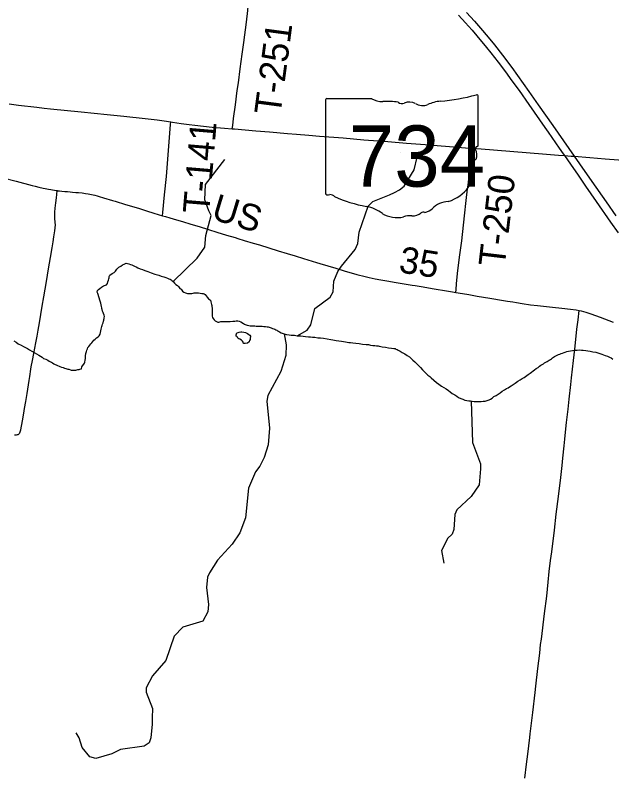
# Model space of a CAD drawing. Extents: x -5.4 to 49.9, y 13.2 to 48.4.
# Drawn here: x 30.593 to 31.879, y 42.099 to 43.736 of the extents above; entities that cross this region are included whole.
import ezdxf

# ---------------------------------------------------------------- set-up
doc = ezdxf.new("R2010")
doc.units = 0
for name, color, linetype in [('GM_X_County_Road', 7, 'Continuous'), ('GM_X_County_Road_Text', 7, 'Continuous'), ('GM_X_Minor_Lake', 7, 'Continuous'), ('GM_X_Minor_River', 7, 'Continuous'), ('GM_X_State_Location', 7, 'Continuous'), ('GM_X_State_Route', 7, 'Continuous'), ('GM_X_State_Shield', 7, 'Continuous'), ('GM_X_Township_Road', 7, 'Continuous'), ('GM_X_Township_Road_Text', 7, 'Continuous'), ('GM_X_US_Route', 7, 'Continuous')]:
    doc.layers.add(name, color=color, linetype=linetype)

msp = doc.modelspace()

# ---------------------------------------------------------------- linework, layer by layer
at = {"layer": 'GM_X_County_Road'}
for points in [[(30.5673, 43.3856), (30.595, 43.3783), (30.6298, 43.3691), (30.6358, 43.3675), (30.6442, 43.3654), (30.6533, 43.3633), (30.6575, 43.3623), (30.6648, 43.3608), (30.6697, 43.36), (30.673, 43.3593), (30.6774, 43.3586), (30.6811, 43.3581), (30.6833, 43.3579)], [(30.6833, 43.3579), (30.6843, 43.3577), (30.6888, 43.3574), (30.6938, 43.3569), (30.6999, 43.3563), (30.7055, 43.3558), (30.7117, 43.3553), (30.7166, 43.3548), (30.7234, 43.3542), (30.7296, 43.3536), (30.7376, 43.3528), (30.7444, 43.3519), (30.7505, 43.351), (30.7571, 43.3496), (30.7644, 43.348), (30.7698, 43.3466), (30.7739, 43.3454), (30.7835, 43.3426), (30.8025, 43.3369), (30.8084, 43.3351), (30.831, 43.3282), (30.8434, 43.3244), (30.8607, 43.3191), (30.8761, 43.3144), (30.8915, 43.3096), (30.9106, 43.3038), (30.9108, 43.3038)], [(30.9108, 43.3038), (30.9171, 43.3019), (30.9261, 43.2993), (30.9409, 43.2949), (30.9534, 43.2912), (30.9713, 43.2858), (30.9897, 43.2803), (31.0099, 43.2741), (31.0277, 43.2686), (31.0486, 43.2623), (31.067, 43.2568), (31.0729, 43.255), (31.0866, 43.2508), (31.1062, 43.245), (31.1198, 43.2409), (31.1394, 43.2349), (31.1601, 43.2284), (31.1791, 43.2226), (31.1963, 43.2174), (31.2148, 43.2118), (31.2428, 43.2034), (31.2499, 43.2012), (31.2671, 43.196), (31.2844, 43.1908), (31.3022, 43.1854), (31.3297, 43.1774), (31.3471, 43.1727), (31.3562, 43.1706), (31.369, 43.168), (31.3812, 43.1659), (31.3941, 43.1636), (31.4139, 43.1602), (31.4487, 43.1544), (31.4555, 43.1533), (31.4684, 43.1512), (31.4959, 43.1466), (31.5229, 43.1421), (31.5357, 43.1399), (31.5426, 43.1387)], [(31.5426, 43.1387), (31.5572, 43.1362), (31.5706, 43.134), (31.589, 43.1309), (31.6159, 43.1263), (31.6459, 43.1212), (31.6539, 43.1199), (31.6656, 43.118), (31.6735, 43.1167), (31.6858, 43.1147), (31.7036, 43.1121), (31.7191, 43.1102), (31.7512, 43.1068), (31.7716, 43.1047), (31.7901, 43.1028), (31.8024, 43.101), (31.8087, 43.0998)], [(31.6918, 42.0924), (31.6955, 42.1226), (31.6982, 42.1442), (31.7024, 42.18), (31.7034, 42.188), (31.7089, 42.2337), (31.7138, 42.2769), (31.7155, 42.2905), (31.7199, 42.3287), (31.7236, 42.3615), (31.7257, 42.38), (31.7272, 42.3917), (31.7341, 42.4472), (31.7388, 42.4843), (31.7418, 42.5144), (31.7443, 42.5373), (31.7471, 42.5608), (31.7495, 42.5799), (31.7552, 42.6262), (31.7593, 42.6607), (31.7642, 42.6989), (31.7691, 42.7402), (31.772, 42.7656), (31.7737, 42.7816), (31.7765, 42.8082), (31.778, 42.8224), (31.7795, 42.8378), (31.7816, 42.8582), (31.7849, 42.8873), (31.7874, 42.9089), (31.7906, 42.9404), (31.7922, 42.9546), (31.7966, 42.9922), (31.8001, 43.0231), (31.804, 43.0596), (31.8064, 43.0799), (31.8087, 43.0998)], [(31.8087, 43.0998), (31.8133, 43.0989), (31.8234, 43.0962), (31.834, 43.0927), (31.8537, 43.0852), (31.8822, 43.0743)]]:
    msp.add_lwpolyline(points, dxfattribs=at)
at = {"layer": 'GM_X_Minor_Lake'}
msp.add_lwpolyline([(31.0712, 43.0518), (31.0757, 43.0532), (31.0792, 43.0536), (31.0814, 43.0539), (31.086, 43.0527), (31.0894, 43.0523), (31.092, 43.0511), (31.0939, 43.0504), (31.0969, 43.048), (31.0988, 43.0465), (31.1003, 43.0442), (31.0995, 43.0397), (31.0995, 43.037), (31.0983, 43.0347), (31.0971, 43.0321), (31.0937, 43.0295), (31.0884, 43.0288), (31.0853, 43.0284), (31.0842, 43.0315), (31.0831, 43.0334), (31.0805, 43.0361), (31.0775, 43.0376), (31.0748, 43.0388), (31.0726, 43.04), (31.0711, 43.0426), (31.0696, 43.0446), (31.0696, 43.0472), (31.0708, 43.0518), (31.0712, 43.0518)], dxfattribs=at)
at = {"layer": 'GM_X_Minor_River'}
for points in [[(31.2009, 43.0454), (31.2224, 43.0576), (31.2306, 43.0689), (31.2392, 43.1037), (31.2722, 43.1281), (31.2781, 43.1398), (31.28, 43.1629), (31.2887, 43.184), (31.2965, 43.1949), (31.3259, 43.2312), (31.3315, 43.244), (31.3346, 43.2683), (31.3541, 43.3241), (31.3638, 43.3342), (31.4, 43.3487), (31.4104, 43.3542), (31.4215, 43.3594), (31.4311, 43.3672), (31.4529, 43.4025), (31.4598, 43.4297)], [(30.9335, 43.162), (30.9853, 43.2127), (31.0016, 43.236), (31.0036, 43.261), (31.0157, 43.3045), (31.0102, 43.3141), (31.0019, 43.3378), (31.0029, 43.3708), (31.0448, 43.4247)], [(30.6993, 42.9758), (30.7019, 42.975), (30.7042, 42.9742), (30.7065, 42.9734), (30.7084, 42.973), (30.7118, 42.9718), (30.7136, 42.9714), (30.7159, 42.971), (30.7182, 42.971), (30.7205, 42.971), (30.7239, 42.9713), (30.7277, 42.9724), (30.7307, 42.9728), (30.7326, 42.9731), (30.7357, 42.9738), (30.7369, 42.9784), (30.7423, 42.9859), (30.7427, 42.9886), (30.7435, 42.9927), (30.7443, 42.9965), (30.7447, 43.0019), (30.7455, 43.0068), (30.7459, 43.0094), (30.7463, 43.0117), (30.7471, 43.014), (30.7487, 43.017), (30.7498, 43.0197), (30.7517, 43.0219), (30.7541, 43.0249), (30.756, 43.0276), (30.7579, 43.0298), (30.7602, 43.0328), (30.7625, 43.0358), (30.7656, 43.0381), (30.7683, 43.0407), (30.7717, 43.043), (30.774, 43.0448), (30.7763, 43.0486), (30.7771, 43.0524), (30.7775, 43.0558), (30.7783, 43.0592), (30.7791, 43.0623), (30.7799, 43.0653), (30.7807, 43.0676), (30.7815, 43.0702), (30.7823, 43.0729), (30.7831, 43.0767), (30.7838, 43.0785), (30.7842, 43.0804), (30.7846, 43.0823), (30.785, 43.0842), (30.7851, 43.0869), (30.7847, 43.0896), (30.7836, 43.093), (30.7825, 43.0957), (30.7814, 43.0983), (30.7807, 43.1018), (30.7799, 43.1037), (30.78, 43.1056), (30.7792, 43.1082), (30.7785, 43.1117), (30.7778, 43.1158), (30.7763, 43.1197), (30.7708, 43.1364), (30.7697, 43.1391), (30.7705, 43.1425), (30.7728, 43.1452), (30.7751, 43.147), (30.7789, 43.15), (30.7808, 43.1515), (30.7831, 43.1526), (30.7858, 43.1538), (30.7877, 43.1545), (30.7896, 43.1552), (30.7919, 43.1582), (30.7927, 43.1617), (30.7939, 43.1651), (30.7947, 43.1677), (30.7954, 43.1704), (30.7958, 43.1726), (30.797, 43.1757), (30.802, 43.1794), (30.8066, 43.1813), (30.8089, 43.1846), (30.8123, 43.1884), (30.8162, 43.1929), (30.8208, 43.1955), (30.8242, 43.1982), (30.828, 43.1996), (30.8322, 43.2019), (30.8379, 43.1999), (30.8417, 43.1987), (30.8447, 43.1979), (30.8469, 43.1964), (30.85, 43.1952), (30.8537, 43.1936), (30.8575, 43.1917), (30.8624, 43.1897), (30.8673, 43.1878), (30.8726, 43.1855), (30.8791, 43.1835)], [(30.8791, 43.1835), (30.8859, 43.1807), (30.8938, 43.178), (30.9029, 43.1756), (30.9078, 43.1737), (30.9131, 43.1721), (30.9176, 43.1705), (30.9214, 43.1693), (30.9244, 43.1682), (30.9271, 43.167), (30.9289, 43.1654), (30.9312, 43.1639), (30.9335, 43.162), (30.9361, 43.1589), (30.9391, 43.1554), (30.9429, 43.1535), (30.9447, 43.1516), (30.9462, 43.1493), (30.9481, 43.1474), (30.9504, 43.1454), (30.9519, 43.1435), (30.9534, 43.1416), (30.9564, 43.1389), (30.9598, 43.1374), (30.9643, 43.1365), (30.9681, 43.1365), (30.9715, 43.1365), (30.9738, 43.1364), (30.9765, 43.1372), (30.9787, 43.1375), (30.9882, 43.1374), (30.9916, 43.137), (30.995, 43.1366), (30.9985, 43.1362), (31.0003, 43.1358), (31.0026, 43.1338), (31.0045, 43.1315), (31.0071, 43.1281), (31.0097, 43.125), (31.012, 43.1231), (31.0139, 43.1219), (31.0146, 43.1181), (31.0157, 43.1158), (31.0164, 43.1124), (31.0168, 43.1105), (31.0171, 43.1086), (31.0175, 43.1048), (31.0174, 43.1014), (31.0174, 43.098), (31.0174, 43.0938), (31.0177, 43.0904), (31.0177, 43.0877), (31.0184, 43.0846), (31.0195, 43.0824), (31.0218, 43.0797), (31.024, 43.0777), (31.0267, 43.0762), (31.0297, 43.0746), (31.0316, 43.0746), (31.0361, 43.0757), (31.0422, 43.076), (31.0502, 43.0759), (31.0563, 43.0762), (31.0619, 43.0766), (31.0661, 43.0769), (31.0695, 43.0772), (31.0726, 43.0772), (31.076, 43.0768), (31.079, 43.0756), (31.085, 43.0717), (31.0869, 43.0702), (31.0888, 43.0694), (31.0907, 43.0686), (31.0933, 43.0678), (31.0964, 43.0674), (31.0994, 43.067), (31.1021, 43.067), (31.1062, 43.0666), (31.1093, 43.0665), (31.1123, 43.0661), (31.1153, 43.0661), (31.1188, 43.066), (31.1218, 43.066), (31.1252, 43.0656), (31.129, 43.0655), (31.1328, 43.0651), (31.1358, 43.0647), (31.1385, 43.0643), (31.1404, 43.0639), (31.1426, 43.0631), (31.1449, 43.0623), (31.1475, 43.0612), (31.1506, 43.06), (31.1528, 43.0592), (31.1547, 43.058), (31.1566, 43.0573), (31.1585, 43.0561), (31.1604, 43.0549), (31.163, 43.0534), (31.1664, 43.0518), (31.1725, 43.0495)], [(31.1725, 43.0495), (31.1768, 43.0254), (31.1764, 43.003), (31.1659, 42.9686), (31.1373, 42.9164), (31.1352, 42.9043), (31.1414, 42.8464), (31.1381, 42.81), (31.13, 42.7832), (31.1206, 42.764), (31.1109, 42.7524), (31.0959, 42.717), (31.0894, 42.6533), (31.0771, 42.6205), (31.0604, 42.5961), (31.0294, 42.5617), (31.0119, 42.5347), (31.0075, 42.5249), (31.0053, 42.5029), (31.0095, 42.466), (31.0081, 42.4509), (30.9972, 42.4305), (30.9541, 42.4177), (30.9359, 42.3979), (30.9176, 42.3458), (30.8886, 42.3129), (30.8752, 42.2869), (30.8751, 42.2774), (30.8888, 42.2426), (30.8881, 42.2221), (30.8882, 42.2088), (30.8854, 42.1789), (30.8815, 42.1687), (30.8707, 42.1609), (30.8202, 42.1539), (30.8011, 42.1444), (30.7668, 42.1347), (30.7536, 42.138), (30.7376, 42.1584), (30.7308, 42.1794), (30.7242, 42.1898)], [(31.1725, 43.0495), (31.1781, 43.0479), (31.1838, 43.0471), (31.188, 43.0466), (31.1914, 43.0462), (31.1948, 43.0462), (31.1978, 43.0458), (31.2009, 43.0454), (31.2047, 43.0453), (31.2088, 43.0449), (31.2138, 43.0445), (31.2187, 43.0436), (31.2251, 43.0432), (31.2297, 43.0428), (31.2342, 43.0423), (31.2392, 43.0419), (31.2452, 43.0411), (31.2513, 43.0406), (31.2573, 43.0398), (31.2733, 43.0373), (31.2778, 43.0365), (31.2846, 43.0353), (31.2964, 43.0333), (31.3051, 43.032), (31.3123, 43.0308), (31.3161, 43.0304), (31.321, 43.0303), (31.3274, 43.0295), (31.3342, 43.0283), (31.3414, 43.0271), (31.3498, 43.0266), (31.3543, 43.0262), (31.3589, 43.025), (31.3638, 43.0245), (31.3684, 43.0241), (31.3718, 43.0233), (31.3752, 43.0233), (31.3775, 43.0232), (31.3812, 43.0221), (31.3843, 43.0216), (31.3911, 43.0208), (31.3975, 43.0196), (31.404, 43.0184), (31.4089, 43.0179), (31.4119, 43.0175), (31.4138, 43.0167), (31.4161, 43.016), (31.4187, 43.0144), (31.4225, 43.0121), (31.4274, 43.0094), (31.4327, 43.0063), (31.4376, 43.0024), (31.4428, 42.9997), (31.4466, 42.9966), (31.4504, 42.9928), (31.4545, 42.9893), (31.4579, 42.9855), (31.462, 42.9812), (31.4665, 42.977), (31.471, 42.972), (31.4751, 42.9674), (31.4793, 42.9636), (31.4827, 42.9605), (31.4868, 42.9574), (31.4898, 42.9543), (31.5011, 42.9447), (31.5064, 42.9412), (31.5116, 42.937), (31.5173, 42.9335), (31.5222, 42.9308), (31.5267, 42.9277), (31.5308, 42.9246), (31.5346, 42.9208), (31.5406, 42.918), (31.5448, 42.915), (31.5489, 42.9126), (31.5535, 42.9103), (31.558, 42.9084), (31.5625, 42.9068), (31.5667, 42.906), (31.5705, 42.9052), (31.5735, 42.9048), (31.5758, 42.9047), (31.5781, 42.9043), (31.5822, 42.9039), (31.5853, 42.9039), (31.5883, 42.9038), (31.5928, 42.9038), (31.5978, 42.9037), (31.602, 42.9041), (31.6061, 42.9044), (31.6103, 42.9055), (31.6145, 42.907), (31.6176, 42.9088), (31.621, 42.9111), (31.6248, 42.9144), (31.6298, 42.9167), (31.634, 42.9197), (31.6382, 42.9226), (31.6424, 42.9256), (31.6478, 42.929)], [(30.5902, 43.034), (30.5948, 43.0313), (30.5993, 43.0282), (30.6061, 43.0247), (30.6106, 43.022), (30.6151, 43.02), (30.6193, 43.0177), (30.6238, 43.015), (30.6291, 43.0119), (30.6442, 43.0034), (30.6476, 43.0014), (30.651, 42.9991), (30.6543, 42.9964), (30.6593, 42.9945), (30.663, 42.9925), (30.666, 42.9906), (30.6687, 42.9894), (30.671, 42.9882), (30.6736, 42.9867), (30.6762, 42.9851), (30.6789, 42.9836), (30.6815, 42.9824), (30.6838, 42.9813), (30.6876, 42.9797), (30.6894, 42.9789), (30.6925, 42.9777), (30.6962, 42.9766), (30.6993, 42.9758)], [(31.6478, 42.929), (31.6523, 42.9316), (31.6558, 42.9331), (31.6584, 42.935), (31.6619, 42.9376), (31.6661, 42.9406), (31.6707, 42.9432), (31.6768, 42.9473), (31.6818, 42.9503), (31.686, 42.9529), (31.6898, 42.9551), (31.6928, 42.9578), (31.6959, 42.9596), (31.699, 42.9619), (31.7028, 42.9645), (31.7127, 42.9716), (31.7162, 42.9746), (31.72, 42.9772), (31.723, 42.9798), (31.7261, 42.9817), (31.7288, 42.9836), (31.7315, 42.9851), (31.7341, 42.9869), (31.7372, 42.9884), (31.7395, 42.9899), (31.7421, 42.9914), (31.7441, 42.9925), (31.7471, 42.994), (31.749, 42.9959), (31.7509, 42.9974), (31.7532, 42.9989), (31.7555, 43.0004), (31.7582, 43.0019), (31.7612, 43.0037), (31.7643, 43.0048), (31.7673, 43.0059), (31.77, 43.007), (31.7727, 43.0081), (31.7761, 43.0092), (31.7788, 43.01), (31.7822, 43.0111), (31.7856, 43.0118), (31.7898, 43.0129), (31.7944, 43.0136), (31.7993, 43.0139), (31.8046, 43.0142), (31.8095, 43.0146), (31.8137, 43.0145), (31.8175, 43.0141), (31.8232, 43.0133), (31.8274, 43.0125), (31.8323, 43.012), (31.8384, 43.0108), (31.8448, 43.0096), (31.8512, 43.008), (31.8576, 43.0053), (31.8644, 43.0029), (31.8701, 43.001), (31.8743, 42.999), (31.8777, 42.9975), (31.8811, 42.9948)], [(31.5758, 42.9047), (31.5789, 42.8153), (31.5959, 42.7694), (31.5961, 42.7588), (31.5932, 42.7239), (31.5757, 42.6991), (31.5449, 42.6701), (31.5405, 42.6599), (31.5384, 42.628), (31.5348, 42.6175), (31.5252, 42.6085), (31.5193, 42.5961), (31.5122, 42.5826), (31.517, 42.5555)]]:
    msp.add_lwpolyline(points, dxfattribs=at)
at = {"layer": 'GM_X_State_Route'}
for points in [[(30.5797, 43.5446), (30.6001, 43.5422), (30.6395, 43.5374), (30.6556, 43.5357), (30.6692, 43.5342), (30.7353, 43.5274), (30.7915, 43.5216), (30.8268, 43.518), (30.8733, 43.5132), (30.8993, 43.5102), (30.9141, 43.5083), (30.9283, 43.5063), (30.932, 43.5057), (30.951, 43.5026), (30.9682, 43.5), (30.9799, 43.4986), (31.0176, 43.4949), (31.0442, 43.4928), (31.0609, 43.4913), (31.0659, 43.4909), (31.1117, 43.4867), (31.1408, 43.4843), (31.1798, 43.4809), (31.1996, 43.4792), (31.2262, 43.4773), (31.2492, 43.4755), (31.2999, 43.4714), (31.3445, 43.4676), (31.3965, 43.4636), (31.4362, 43.4605), (31.4765, 43.4573), (31.5551, 43.4509), (31.572, 43.4497)], [(31.572, 43.4497), (31.578, 43.4492), (31.5978, 43.4477), (31.6944, 43.4399), (31.7384, 43.4366), (31.7644, 43.4345)], [(31.7644, 43.4345), (31.777, 43.4335), (31.7917, 43.4324), (31.7981, 43.4318), (31.832, 43.4291), (31.8648, 43.4267), (31.9515, 43.4199), (32.0544, 43.4114)]]:
    msp.add_lwpolyline(points, dxfattribs=at)
at = {"layer": 'GM_X_State_Shield'}
for p, q in [((31.5913, 43.4563), (31.5913, 43.5609)), ((31.2617, 43.5525), (31.2617, 43.3524)), ((31.3615, 43.556), (31.2649, 43.556)), ((31.5912, 43.4563), (31.5913, 43.4563))]:
    msp.add_line(p, q, dxfattribs=at)
for centre, major_axis, start_param, end_param in [((31.4739, 43.8288), (0.3495, 0), 4.814394, 5.042369), ((31.5876, 43.5614), (0.00367, 0), 6.141152, 7.989035), ((31.2655, 43.553), (0.00382, 0), 1.712693, 3.28349), ((31.3844, 43.5792), (0.037, 0), 4.042523, 4.731795), ((31.3967, 43.4436), (0.133, 0), 1.404758, 1.657858), ((31.4269, 43.554), (0.0107, 0), 3.836095, 5.185415), ((31.4426, 43.5309), (0.0222, 0), 0.950623, 2.079405), ((31.4713, 43.5626), (0.0267, 0), 4.081561, 5.145723), ((31.5184, 43.4949), (0.0703, 0), 1.699011, 2.107814), ((31.5904, 43.4486), (0.00568, 0), 1.883978, 3.671073), ((31.5543, 43.4353), (0.0341, 0), 5.934695, 6.695948), ((31.5874, 43.4559), (0.00393, 0), 5.05454, 6.418171), ((31.6044, 43.4125), (0.0248, 0), 2.387724, 3.262537), ((31.4934, 43.3991), (0.0874, 0), 5.101752, 6.440018), ((31.2655, 43.352), (0.00385, 0), 3.00124, 4.508301), ((31.2661, 43.3725), (0.0294, 0), 4.665946, 4.897461), ((31.2721, 43.3409), (0.0106, 0), 0.519207, 1.627899), ((31.4059, 43.5207), (0.2524, 0), 4.195997, 4.488961), ((31.5303, 43.2962), (0.0479, 0), 1.647645, 2.488434), ((31.3307, 43.2625), (0.079, 0), 0.823519, 1.323587), ((31.4696, 43.333), (0.0282, 0), 4.937069, 5.64225), ((31.4161, 43.3399), (0.0501, 0), 4.026481, 4.996735), ((31.445, 43.2707), (0.0412, 0), 1.495662, 1.94098), ((31.4487, 43.3249), (0.0267, 0), 4.691044, 5.507374), ((31.4728, 43.3055), (0.00752, 0), 1.147584, 2.315152)]:
    msp.add_ellipse(centre, major_axis=major_axis, ratio=0.8, start_param=start_param, end_param=end_param, dxfattribs=at)
at = {"layer": 'GM_X_Township_Road'}
for points in [[(31.0609, 43.4913), (31.0618, 43.4981), (31.0639, 43.5135), (31.0675, 43.5425), (31.0717, 43.5733), (31.074, 43.5899), (31.0781, 43.6201), (31.0824, 43.6521), (31.0859, 43.6767), (31.0916, 43.7211), (31.0945, 43.7458), (31.0962, 43.765), (31.0975, 43.7811), (31.1004, 43.8176), (31.1045, 43.8672), (31.1061, 43.8887)], [(30.9108, 43.3038), (30.9115, 43.3111), (30.9148, 43.3492), (30.9189, 43.3885), (30.9257, 43.4725), (30.9278, 43.5003), (30.9283, 43.5063)], [(31.5682, 43.3619), (31.5692, 43.37), (31.5734, 43.4095), (31.577, 43.4403), (31.578, 43.4492)], [(30.6394, 43.0406), (30.6401, 43.0445), (30.6424, 43.0574), (30.6453, 43.0732), (30.6512, 43.1087), (30.6545, 43.129), (30.6601, 43.162), (30.6646, 43.1895), (30.6688, 43.214), (30.6725, 43.2348), (30.6747, 43.2477), (30.6764, 43.2581), (30.6784, 43.2716), (30.6793, 43.2778), (30.6796, 43.2842), (30.6792, 43.2895), (30.6786, 43.2988), (30.6783, 43.3056), (30.6785, 43.3118), (30.6791, 43.3199), (30.6804, 43.3316), (30.6817, 43.3427), (30.6824, 43.3495), (30.6833, 43.3579)], [(31.5426, 43.1387), (31.5432, 43.1449), (31.5442, 43.1572), (31.5464, 43.1795), (31.551, 43.2146), (31.5555, 43.2497), (31.5615, 43.3033), (31.5653, 43.3367), (31.5682, 43.3619)], [(30.5914, 42.8321), (30.5939, 42.8319), (30.5958, 42.8319), (30.5979, 42.8323), (30.5992, 42.8329), (30.6006, 42.8336), (30.6018, 42.8347), (30.6028, 42.8361), (30.6039, 42.8381), (30.6047, 42.8403), (30.6052, 42.8427), (30.6086, 42.8623), (30.6116, 42.8788), (30.6133, 42.8886), (30.6157, 42.9038), (30.6185, 42.921), (30.6229, 42.9486), (30.6242, 42.9572), (30.6269, 42.9731), (30.6277, 42.978), (30.6302, 42.9921), (30.633, 43.0067), (30.6373, 43.0299), (30.6394, 43.0406)]]:
    msp.add_lwpolyline(points, dxfattribs=at)
at = {"layer": 'GM_X_US_Route'}
for points in [[(31.5661, 43.7415), (31.5832, 43.7227), (31.5963, 43.7078), (31.6127, 43.6883), (31.626, 43.6719), (31.6432, 43.6499), (31.6634, 43.6231), (31.6759, 43.6061), (31.7003, 43.5716), (31.7206, 43.5426), (31.7516, 43.4983), (31.7981, 43.4318), (31.8097, 43.4153), (31.8361, 43.3777), (31.8668, 43.3339), (31.8881, 43.3033)], [(31.5485, 43.7361), (31.5637, 43.7196), (31.5703, 43.7122), (31.5777, 43.7038), (31.5881, 43.6914), (31.6087, 43.6665), (31.6184, 43.6544), (31.6342, 43.6345), (31.6523, 43.6107), (31.6617, 43.5976), (31.6791, 43.5733), (31.7002, 43.5433), (31.7347, 43.4939), (31.7418, 43.4837), (31.7657, 43.4496), (31.7742, 43.4374), (31.7743, 43.4373)], [(31.7743, 43.4373), (31.777, 43.4335), (31.79, 43.4151), (31.8065, 43.391), (31.8221, 43.3678), (31.8451, 43.3347), (31.8761, 43.2903), (31.8927, 43.2671)]]:
    msp.add_lwpolyline(points, dxfattribs=at)

# ---------------------------------------------------------------- texts
at = {"layer": 'GM_X_County_Road_Text'}
for s, rotation, p in [('US', 343.0959, (31.0133, 43.2974)), ('35', 351.2025, (31.418, 43.1822))]:
    msp.add_text(s, height=0.05682, rotation=rotation, dxfattribs=at).set_placement(p)
at = {"layer": 'GM_X_State_Location'}
for s in ['s', 'r']:
    msp.add_text(s, height=0.000189, dxfattribs=at).set_placement((31.4228, 43.4392))
msp.add_text('734', height=0.000189, rotation=0, dxfattribs=at).set_placement((31.3559, 43.4254))
at = {"layer": 'GM_X_State_Shield'}
msp.add_text('734', height=0.13184, dxfattribs=at).set_placement((31.312, 43.3665))
at = {"layer": 'GM_X_Township_Road_Text'}
for s, rotation, p in [('T-251', 82.4605, (31.1645, 43.5189)), ('T-141', 85.2395, (31.0108, 43.3068)), ('T-250', 83.2978, (31.648, 43.1921))]:
    msp.add_text(s, height=0.05682, rotation=rotation, dxfattribs=at).set_placement(p)

doc.saveas('drawing.dxf')
